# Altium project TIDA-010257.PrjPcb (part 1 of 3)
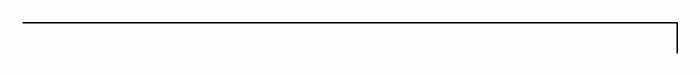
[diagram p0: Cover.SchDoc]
CopyrightYear: 2023; PCB_Layout: Hely Zhang; PCB_Rev: B; PRJ_Customer: Public Release; PRJ_Engineer: Hely Zhang; PRJ_Number: TIDA-010257; PRJ_Title: 10kW Vienna PFC; SCH_Rev: B; TechSupport: http://www.ti.com/support; TID: TIDA-010257
11 sheets, 481 parts. Net scope: hierarchical (ports join the sheet entries above them; power ports are global).
Board file: TIDA-010257.PcbDoc
Sheets:
  Cover.SchDoc
  Main.SchDoc
    PowerStage = PowerStage.SchDoc
    GateDrivers = GateDrivers.SchDoc
    IsolatedPower = IsolatedPower.SchDoc
    Hardware = Hardware.SchDoc
    EMCInputFilter = EMCInputFilter.SchDoc
    InputVoltageSensing = InputVoltageSensing.SchDoc
    OutputVoltageSensing = OutputVoltageSensing.SchDoc
    Controller = Controller.SchDoc
    AuxPower = AuxPower.SchDoc

## Sheet Cover.SchDoc: Cover
size 431 x 279 mm; Date: Not shown in title block; ApprovedBy: Not shown in title block; CheckedBy: Not shown in title block; Author: Not shown in title block; CompanyName: Not shown in title block; DrawnBy: Hely Zhang; Engineer: Not shown in title block; Organization: Not shown in title block; Address1: Not shown in title block; Address2: Not shown in title block; Address3: Not shown in title block; Address4: Not shown in title block; DocumentNumber: 1; Revision: Use project parameter SCH_Rev; SheetNumber: 1; SheetTotal: 11; PageSetup: Record=PageOptions¦CenterHorizontal=True¦CenterVertical=True¦PrintScale=1.00¦XCorrection=1.00¦YCorrection=1.00¦PrintKind=0¦BorderSize=5000000¦LeftOffset=0¦BottomOffset=0¦Orientation=2¦PaperLength=1000¦PaperWidth=1000¦Scale=100¦PaperSource=15¦PrintQuality=600¦MediaType=1¦DitherType=10¦PaperKind=Letter¦PrintScaleMode=1

## Sheet Main.SchDoc: Cover Page
size A4; Date: Not shown in title block; ApprovedBy: Not shown in title block; CheckedBy: Not shown in title block; Author: Not shown in title block; CompanyName: Not shown in title block; DrawnBy: Manish Bhardwaj; Engineer: Not shown in title block; Organization: Not shown in title block; Address1: Not shown in title block; Address2: Not shown in title block; Address3: Not shown in title block; Address4: Not shown in title block; DocumentNumber: 1; Revision: Use project parameter SCH_Rev; SheetNumber: 2; SheetTotal: 11; PageSetup: Record=PageOptions¦CenterHorizontal=True¦CenterVertical=True¦PrintScale=1.00¦XCorrection=1.00¦YCorrection=1.00¦PrintKind=0¦BorderSize=5000000¦LeftOffset=0¦BottomOffset=0¦Orientation=2¦PaperLength=1000¦PaperWidth=1000¦Scale=100¦PaperSource=15¦PrintQuality=-3¦MediaType=1¦DitherType=10¦PrintScaleMode=1¦PaperKind=Letter (8.5 x 11")¦PaperIndex=1
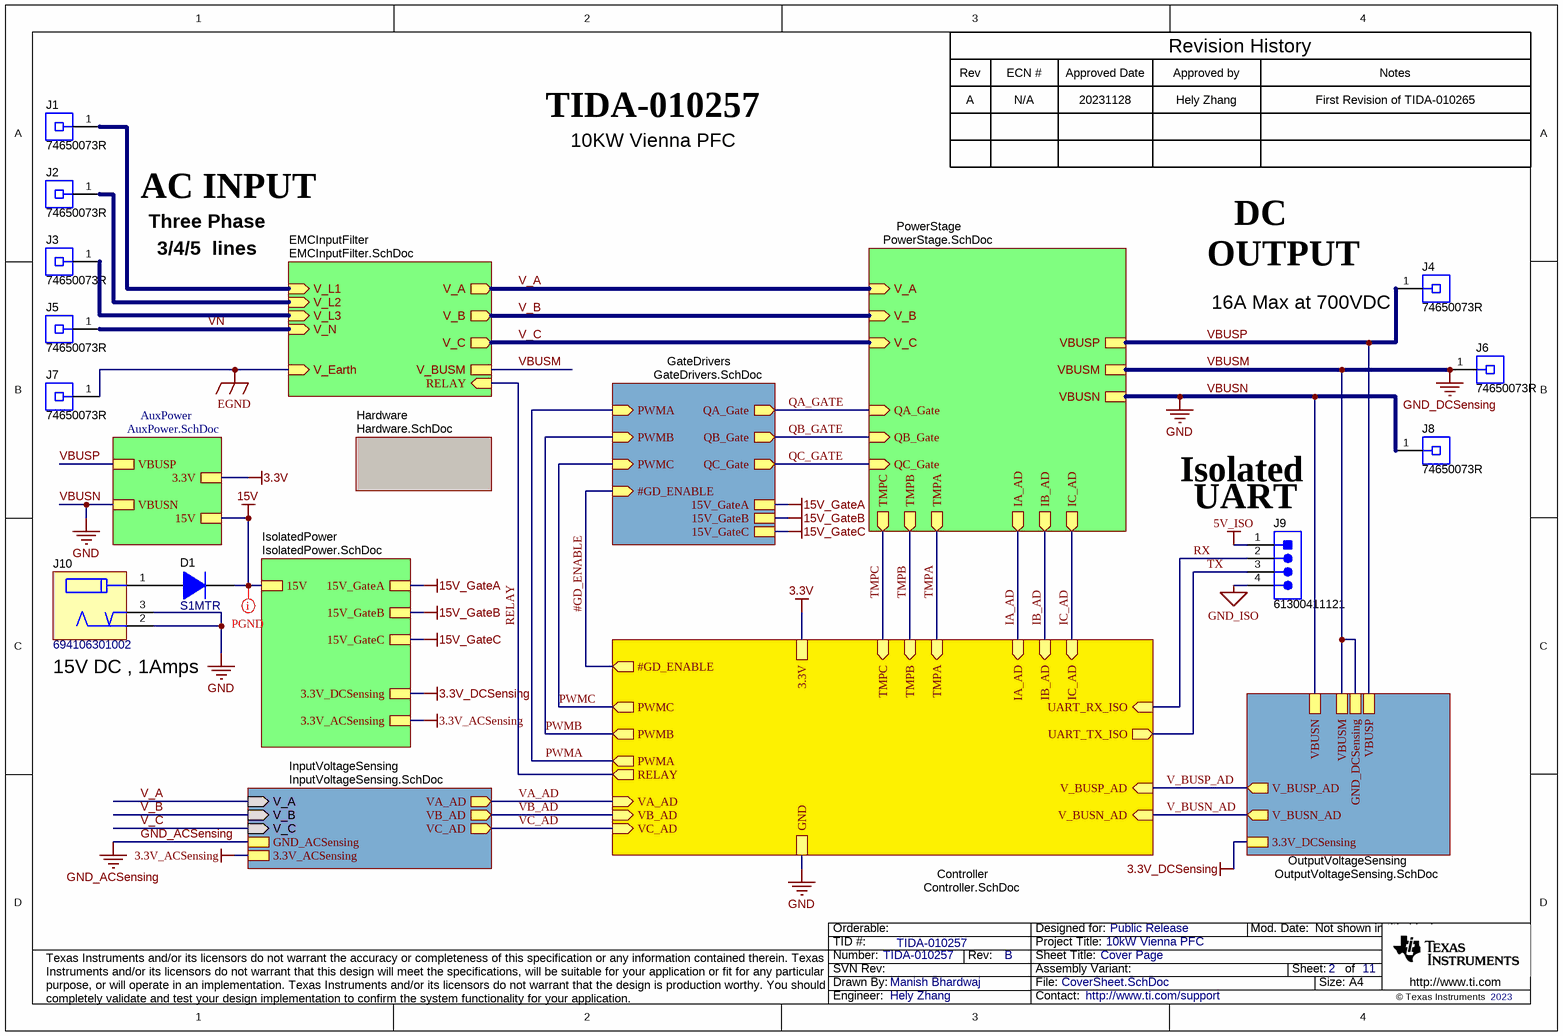
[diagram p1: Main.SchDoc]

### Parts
D1  S1MTR  [SMA]
J1  74650073R  [Wurth_WP-THRBU]
J2  74650073R  [Wurth_WP-THRBU]
J3  74650073R  [Wurth_WP-THRBU]
J4  74650073R  [Wurth_WP-THRBU]
J5  74650073R  [Wurth_WP-THRBU]
J6  74650073R  [Wurth_WP-THRBU]
J7  74650073R  [Wurth_WP-THRBU]
J8  74650073R  [Wurth_WP-THRBU]
J9  61300411121  [WURTH_61300411121]
J10  694106301002  [Wurth_694106301002]

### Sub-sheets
AuxPower = AuxPower.SchDoc: VBUSP, VBUSN, 15V, 3.3V
Controller = Controller.SchDoc: UART_RX_ISO (in), UART_TX_ISO (out), VA_AD (in), VB_AD (in), VC_AD (in), IC_AD (in), IB_AD (in), IA_AD (in), #GD_ENABLE (out), V_BUSN_AD (in), 3.3V, GND, TMPA (in), TMPB (in), TMPC (in), RELAY (out), V_BUSP_AD (in), PWMC (out), PWMB (out), PWMA (out)
EMCInputFilter = EMCInputFilter.SchDoc: V_N (in), V_L2 (in), V_L3 (in), V_L1 (in), V_Earth (in), V_C (out), V_B (out), V_A (out), V_BUSM, RELAY (in)
GateDrivers = GateDrivers.SchDoc: QA_Gate (out), #GD_ENABLE (in), QB_Gate (out), QC_Gate (out), 15V_GateA, 15V_GateB, 15V_GateC, PWMA (in), PWMB (in), PWMC (in)
Hardware = Hardware.SchDoc: no entries
InputVoltageSensing = InputVoltageSensing.SchDoc: V_A (in), V_B (in), V_C (in), VA_AD (out), VB_AD (out), VC_AD (out), GND_ACSensing, 3.3V_ACSensing
IsolatedPower = IsolatedPower.SchDoc: 15V, 15V_GateA, 15V_GateB, 15V_GateC, 3.3V_ACSensing, 3.3V_DCSensing
OutputVoltageSensing = OutputVoltageSensing.SchDoc: VBUSN, VBUSP, VBUSM, V_BUSP_AD (out), V_BUSN_AD (out), 3.3V_DCSensing, GND_DCSensing
PowerStage = PowerStage.SchDoc: V_A (in), V_B (in), V_C (in), VBUSP, VBUSM, VBUSN, QB_Gate (in), QC_Gate (in), IA_AD (out), IB_AD (out), IC_AD (out), QA_Gate (in), TMPA (out), TMPB (out), TMPC (out)

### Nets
3.3V: sheet Controller/3.3V, sheet AuxPower/3.3V
3.3V_ACSensing: sheet IsolatedPower/3.3V_ACSensing, sheet InputVoltageSensing/3.3V_ACSensing
3.3V_DCSensing: sheet IsolatedPower/3.3V_DCSensing, sheet OutputVoltageSensing/3.3V_DCSensing
5V_ISO: J9.1
15V: D1.1(K) ; sheet IsolatedPower/15V, sheet AuxPower/15V
15V_GateA: sheet GateDrivers/15V_GateA, sheet IsolatedPower/15V_GateA
15V_GateB: sheet GateDrivers/15V_GateB, sheet IsolatedPower/15V_GateB
15V_GateC: sheet GateDrivers/15V_GateC, sheet IsolatedPower/15V_GateC
EGND: J7.1 ; sheet EMCInputFilter/V_Earth
GND_ISO: J9.4
VBUSM: J6.1 ; sheet PowerStage/VBUSM, sheet EMCInputFilter/V_BUSM, sheet OutputVoltageSensing/VBUSM, sheet OutputVoltageSensing/GND_DCSensing  [also labelled GND_DCSensing]
VBUSN: J8.1 J10.2 J10.3 ; sheet PowerStage/VBUSN, sheet OutputVoltageSensing/VBUSN, sheet Controller/GND, sheet AuxPower/VBUSN  [also labelled GND]
#GD_ENABLE: sheet GateDrivers/#GD_ENABLE, sheet Controller/#GD_ENABLE
IA_AD: sheet PowerStage/IA_AD, sheet Controller/IA_AD
IB_AD: sheet PowerStage/IB_AD, sheet Controller/IB_AD
IC_AD: sheet PowerStage/IC_AD, sheet Controller/IC_AD
PWMA: sheet GateDrivers/PWMA, sheet Controller/PWMA
PWMB: sheet GateDrivers/PWMB, sheet Controller/PWMB
PWMC: sheet GateDrivers/PWMC, sheet Controller/PWMC
QA_GATE: sheet PowerStage/QA_Gate, sheet GateDrivers/QA_Gate
QB_GATE: sheet PowerStage/QB_Gate, sheet GateDrivers/QB_Gate
QC_GATE: sheet PowerStage/QC_Gate, sheet GateDrivers/QC_Gate
RELAY: sheet EMCInputFilter/RELAY, sheet Controller/RELAY
RX: J9.2 ; sheet Controller/UART_RX_ISO
TMPA: sheet PowerStage/TMPA, sheet Controller/TMPA
TMPB: sheet PowerStage/TMPB, sheet Controller/TMPB
TMPC: sheet PowerStage/TMPC, sheet Controller/TMPC
TX: J9.3 ; sheet Controller/UART_TX_ISO
V_A: sheet PowerStage/V_A, sheet EMCInputFilter/V_A, sheet InputVoltageSensing/V_A
V_B: sheet PowerStage/V_B, sheet EMCInputFilter/V_B, sheet InputVoltageSensing/V_B
V_BUSN_AD: sheet OutputVoltageSensing/V_BUSN_AD, sheet Controller/V_BUSN_AD
V_BUSP_AD: sheet OutputVoltageSensing/V_BUSP_AD, sheet Controller/V_BUSP_AD
V_C: sheet PowerStage/V_C, sheet EMCInputFilter/V_C, sheet InputVoltageSensing/V_C
V_L1: J1.1 ; sheet EMCInputFilter/V_L1
V_L2: J2.1 ; sheet EMCInputFilter/V_L2
V_L3: J3.1 ; sheet EMCInputFilter/V_L3
VA_AD: sheet InputVoltageSensing/VA_AD, sheet Controller/VA_AD
VB_AD: sheet InputVoltageSensing/VB_AD, sheet Controller/VB_AD
VBUSP: J4.1 ; sheet PowerStage/VBUSP, sheet OutputVoltageSensing/VBUSP, sheet AuxPower/VBUSP
VC_AD: sheet InputVoltageSensing/VC_AD, sheet Controller/VC_AD
VN: J5.1 ; sheet EMCInputFilter/V_N
NetD1_2: D1.2(A) J10.1

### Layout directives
net class PGND: 15V

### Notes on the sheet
- Revision History
- Rev
- A
- ECN #
- N/A
- Approved Date
- 20231128
- Approved by
- Hely Zhang
- Notes
- First Revision of TIDA-010265
- TIDA-010257
- 10KW Vienna PFC
- AC INPUT
- Three Phase
- 3/4/5  lines
- DC
- OUTPUT
- (near J4) 16A Max at 700VDC
- Isolated
- (near J9) UART
- (near J10) 15V DC , 1Amps

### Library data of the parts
D1 = CMP-0078438-1: Diode, Standard Recovery Rectifier, 1000 V, 1 A, SMA; Manufacturer: SMC Diode Solutions; SizeAreaWB_mm2: 37.3428; Vr_V: 1kV; SizeArea_mm2: 16.3228; AEC Qualified: N; TJmax_C: 175°C; AEC Category: Q101; Value: 1000V; SizeZ_mm: 2.87; Io_A: 1A; Vf_V: 1.1V; SizeY_mm: 2.92; SizeX_mm: 5.59
J1-J8 = CMP-0078526-1: Power Element Bush, M3, TH; Manufacturer: Wurth Elektronik; Gender: Female; Current_A: 50A; ContactFinish: Tin; CompType: Screw Terminal
J9 = CMP-0054798-2: Header, 2.54 mm, 4x1, Gold, TH; Manufacturer: Wurth Elektronik; Pitch_mm: 2.54; Gender: Male; Row_Count: 1; Cert_UL: Y; Shrouded: N
J10 = CMP-0054778-3: WR-DC DC Power Jack, R/A, TH; Manufacturer: Wurth Elektronik; Gender: Male

## Sheet PowerStage.SchDoc: Power Stage
size A3; Date: Not shown in title block; ApprovedBy: Not shown in title block; CheckedBy: Not shown in title block; Author: Not shown in title block; CompanyName: Not shown in title block; DrawnBy: Hely Zhang; Engineer: Not shown in title block; Organization: Not shown in title block; Address1: Not shown in title block; Address2: Not shown in title block; Address3: Not shown in title block; Address4: Not shown in title block; DocumentNumber: 1; Revision: Use project parameter SCH_Rev; SheetNumber: 4; SheetTotal: 11; PageSetup: Record=PageOptions¦CenterHorizontal=True¦CenterVertical=True¦PrintScale=1.00¦XCorrection=1.00¦YCorrection=1.00¦PrintKind=0¦BorderSize=5000000¦LeftOffset=0¦BottomOffset=0¦Orientation=2¦PaperLength=1000¦PaperWidth=1000¦Scale=100¦PaperSource=15¦PrintQuality=600¦MediaType=1¦DitherType=10¦PaperKind=Letter¦PrintScaleMode=1
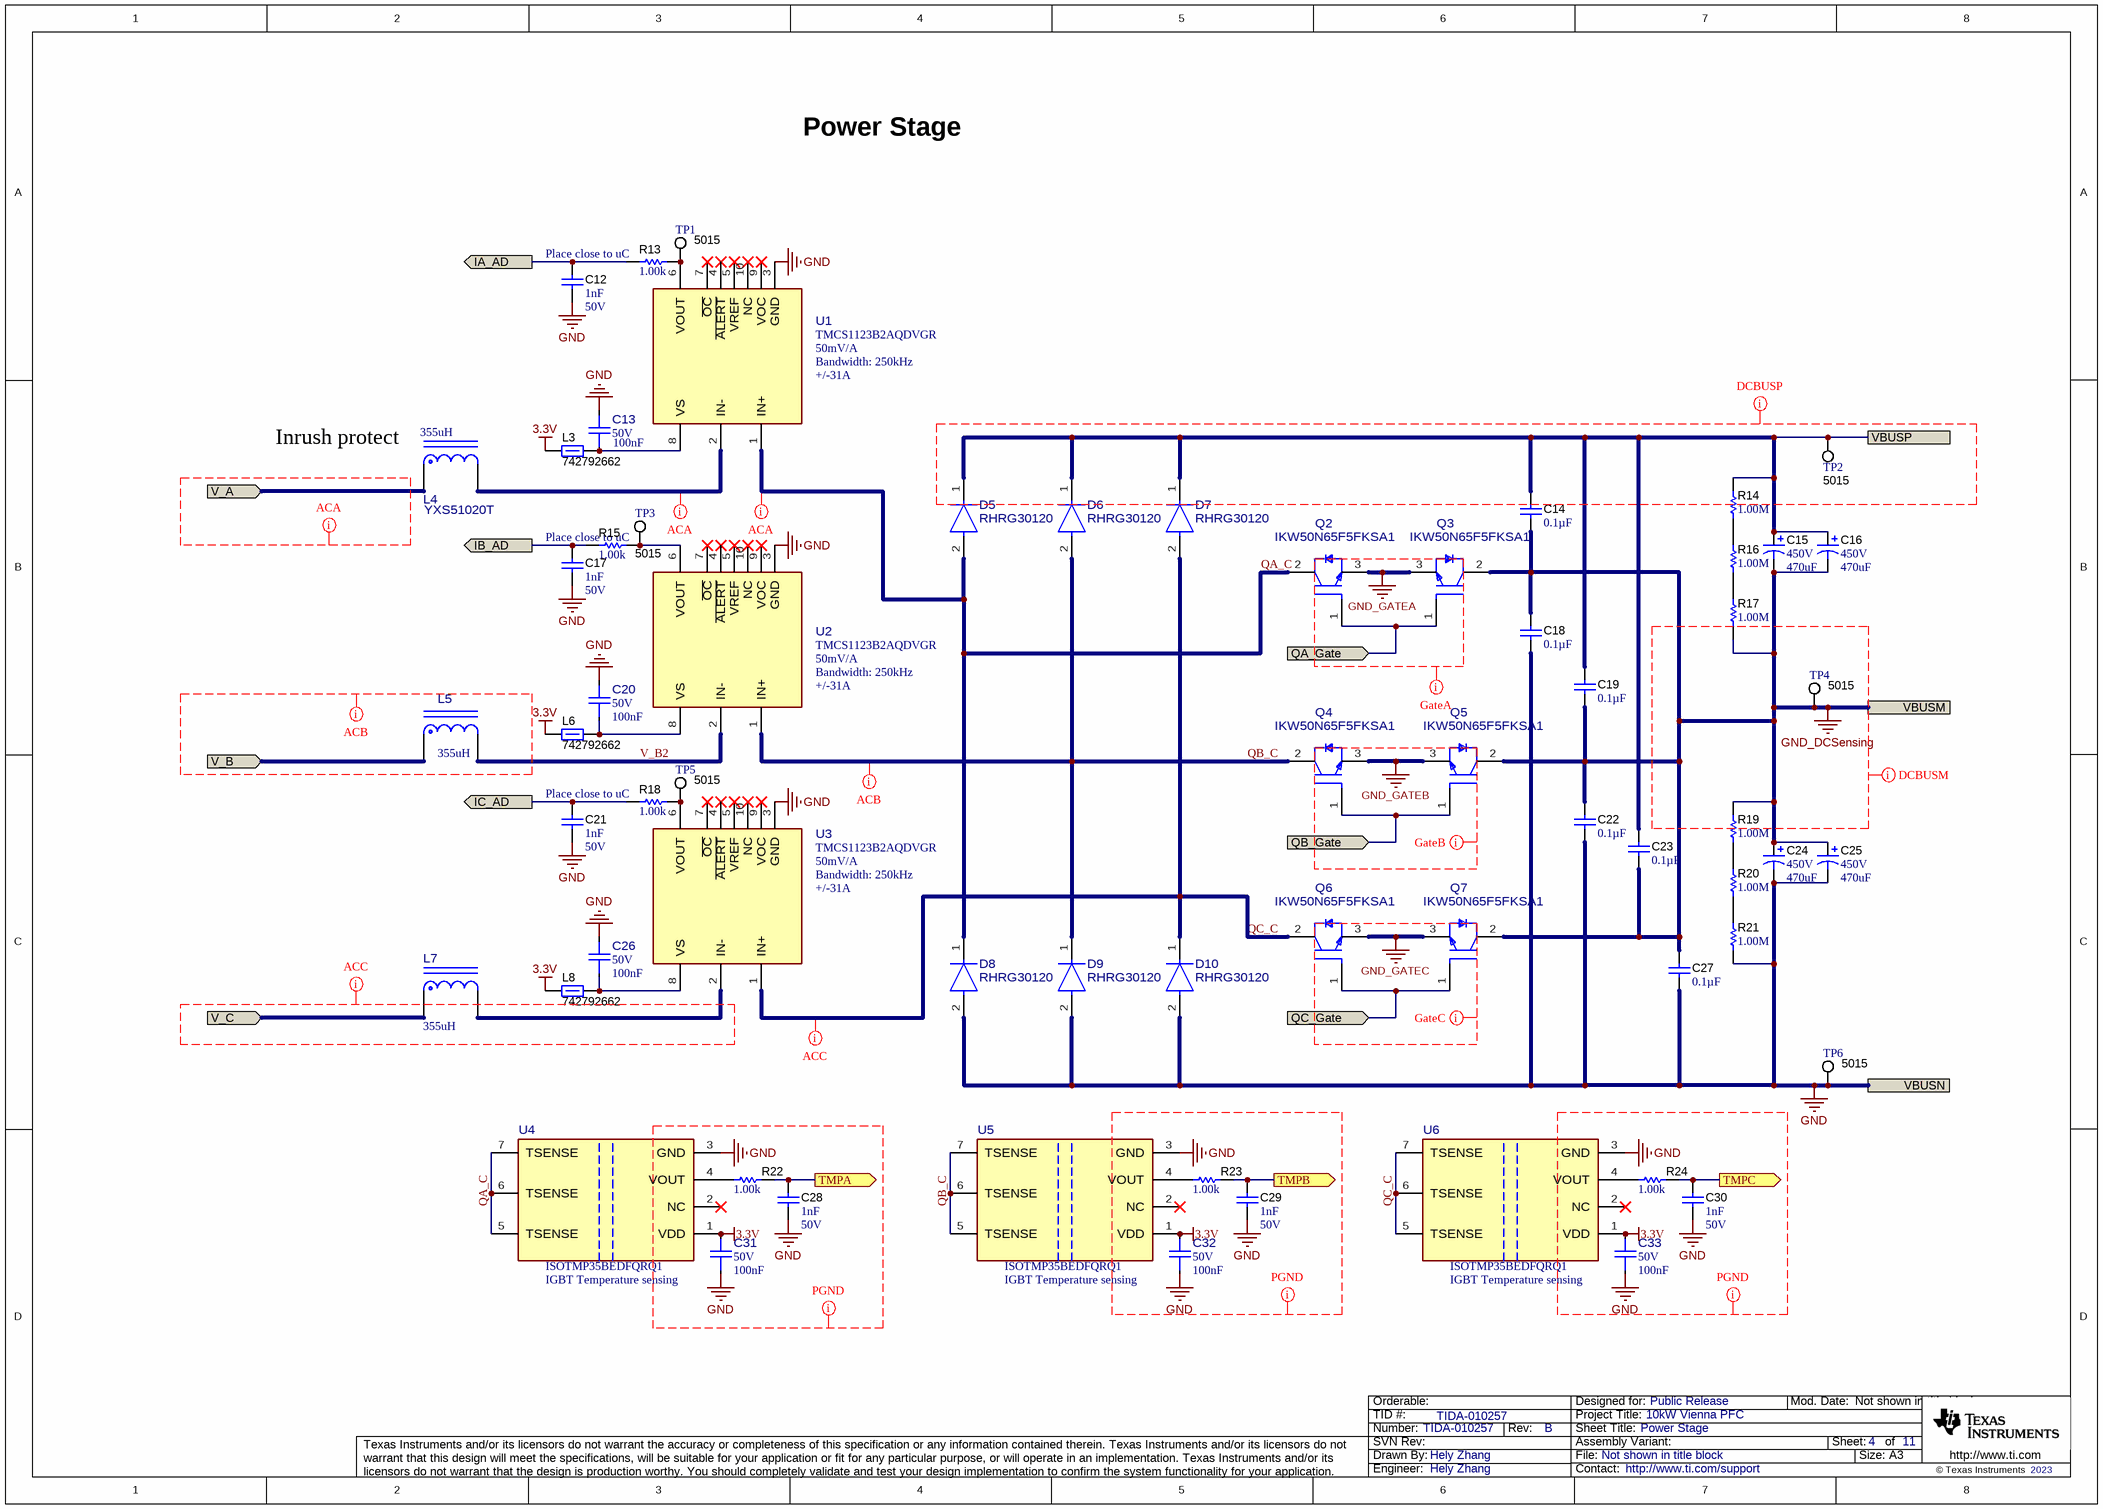
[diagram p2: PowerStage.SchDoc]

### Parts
C12  Cap_F: 1nF  VDC_V: 50V  [0603]  (hidden comment: GRM188R71H102KA01D)
C13  VDC_V: 50V  Cap_F: 100nF  [FP-GCM188R71H104KA57J_0603-MFG]  (hidden comment: GCM188R71H104KA57J)
C14  ValueDisplayed: 0.1µF  [WCAP-FTXX_P15PL20_1800x600]  (hidden comment: 890334025017)
C15  VDC_V: 450V  ValueDisplayed: 470uF  [157PUM-SI_3500x5000]  (hidden comment: MAL215757471E3)
C16  VDC_V: 450V  ValueDisplayed: 470uF  [157PUM-SI_3500x5000]  (hidden comment: MAL215757471E3)
C17  Cap_F: 1nF  VDC_V: 50V  [0603]  (hidden comment: GRM188R71H102KA01D)
C18  ValueDisplayed: 0.1µF  [WCAP-FTXX_P15PL20_1800x600]  (hidden comment: 890334025017)
C19  ValueDisplayed: 0.1µF  [WCAP-FTXX_P15PL20_1800x600]  (hidden comment: 890334025017)
C20  VDC_V: 50V  Cap_F: 100nF  [FP-GCM188R71H104KA57J_0603-MFG]  (hidden comment: GCM188R71H104KA57J)
C21  Cap_F: 1nF  VDC_V: 50V  [0603]  (hidden comment: GRM188R71H102KA01D)
C22  ValueDisplayed: 0.1µF  [WCAP-FTXX_P15PL20_1800x600]  (hidden comment: 890334025017)
C23  ValueDisplayed: 0.1µF  [WCAP-FTXX_P15PL20_1800x600]  (hidden comment: 890334025017)
C24  VDC_V: 450V  ValueDisplayed: 470uF  [157PUM-SI_3500x5000]  (hidden comment: MAL215757471E3)
C25  VDC_V: 450V  ValueDisplayed: 470uF  [157PUM-SI_3500x5000]  (hidden comment: MAL215757471E3)
C26  VDC_V: 50V  Cap_F: 100nF  [FP-GCM188R71H104KA57J_0603-MFG]  (hidden comment: GCM188R71H104KA57J)
C27  ValueDisplayed: 0.1µF  [WCAP-FTXX_P15PL20_1800x600]  (hidden comment: 890334025017)
C28  Cap_F: 1nF  VDC_V: 50V  [0603]  (hidden comment: GRM188R71H102KA01D)
C29  Cap_F: 1nF  VDC_V: 50V  [0603]  (hidden comment: GRM188R71H102KA01D)
C30  Cap_F: 1nF  VDC_V: 50V  [0603]  (hidden comment: GRM188R71H102KA01D)
C31  VDC_V: 50V  Cap_F: 100nF  [FP-GCM188R71H104KA57J_0603-MFG]  (hidden comment: GCM188R71H104KA57J)
C32  VDC_V: 50V  Cap_F: 100nF  [FP-GCM188R71H104KA57J_0603-MFG]  (hidden comment: GCM188R71H104KA57J)
C33  VDC_V: 50V  Cap_F: 100nF  [FP-GCM188R71H104KA57J_0603-MFG]  (hidden comment: GCM188R71H104KA57J)
D5  RHRG30120  [FP-RHRG30120-MFG_HOR]
D6  RHRG30120  [FP-RHRG30120-MFG_HOR]
D7  RHRG30120  [FP-RHRG30120-MFG_HOR]
D8  RHRG30120  [FP-RHRG30120-MFG_HOR]
D9  RHRG30120  [FP-RHRG30120-MFG_HOR]
D10  RHRG30120  [FP-RHRG30120-MFG_HOR]
L3  742792662  [0603]
L4  YXS51020T  value 355uH  [FP-YXS51020T_PTH_IND_58MM0_70MM0-MFG]
L5  value 355uH  [FP-YXS51020T_PTH_IND_58MM0_70MM0-MFG]  (hidden comment: YXS51020T)
L6  742792662  [0603]
L7  value 355uH  [FP-YXS51020T_PTH_IND_58MM0_70MM0-MFG]  (hidden comment: YXS51020T)
L8  742792662  [0603]
Q2  IKW50N65F5FKSA1  [FP-IKW50N65F5FKSA1_HOR_V1]
Q3  IKW50N65F5FKSA1  [FP-IKW50N65F5FKSA1_HOR_V2]
Q4  IKW50N65F5FKSA1  [FP-IKW50N65F5FKSA1_HOR_V1]
Q5  IKW50N65F5FKSA1  [FP-IKW50N65F5FKSA1_HOR_V2]
Q6  IKW50N65F5FKSA1  [FP-IKW50N65F5FKSA1_HOR_V1]
Q7  IKW50N65F5FKSA1  [FP-IKW50N65F5FKSA1_HOR_V2]
R13  ValueDisplayed: 1.00k  [0603]  (hidden comment: RC0603FR-071KL)
R14  ValueDisplayed: 1.00M  [0805_HV]  (hidden comment: ERJ-6ENF1004V)
R15  ValueDisplayed: 1.00k  [0603]  (hidden comment: RC0603FR-071KL)
R16  ValueDisplayed: 1.00M  [0805_HV]  (hidden comment: ERJ-6ENF1004V)
R17  ValueDisplayed: 1.00M  [0805_HV]  (hidden comment: ERJ-6ENF1004V)
R18  ValueDisplayed: 1.00k  [0603]  (hidden comment: RC0603FR-071KL)
R19  ValueDisplayed: 1.00M  [0805_HV]  (hidden comment: ERJ-6ENF1004V)
R20  ValueDisplayed: 1.00M  [0805_HV]  (hidden comment: ERJ-6ENF1004V)
R21  ValueDisplayed: 1.00M  [0805_HV]  (hidden comment: ERJ-6ENF1004V)
R22  ValueDisplayed: 1.00k  [0603]  (hidden comment: RC0603FR-071KL)
R23  ValueDisplayed: 1.00k  [0603]  (hidden comment: RC0603FR-071KL)
R24  ValueDisplayed: 1.00k  [0603]  (hidden comment: RC0603FR-071KL)
TP1  5015  [Testpoint_Keystone_Miniature]
TP2  5015  [Testpoint_Keystone_Miniature]
TP3  5015  [Testpoint_Keystone_Miniature]
TP4  5015  [Testpoint_Keystone_Miniature]
TP5  5015  [Testpoint_Keystone_Miniature]
TP6  5015  [Testpoint_Keystone_Miniature]
U1  TMCS1123B2AQDVGR  [DVG0010A-MFG]
U2  TMCS1123B2AQDVGR  [DVG0010A-MFG]
U3  TMCS1123B2AQDVGR  [DVG0010A-MFG]
U4  ISOTMP35BEDFQRQ1  [DFQ0007A-MFG]
U5  ISOTMP35BEDFQRQ1  [DFQ0007A-MFG]
U6  ISOTMP35BEDFQRQ1  [DFQ0007A-MFG]

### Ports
IA_AD (out), IB_AD (out), IC_AD (out), QA_Gate (in), QB_Gate (in), QC_Gate (in), TMPA (out), TMPB (out), TMPC (out), V_A (in), V_B (in), V_C (in), VBUSM, VBUSN, VBUSP

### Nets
3.3V: C31.2 C32.2 C33.2 L3.1 L6.1 L8.1 U4.1(VDD) U5.1(VDD) U6.1(VDD)
GND: C12.2 C13.2 C17.2 C18.2 C20.2 C21.2 C22.2 C24.2(-) C25.2(-) C26.2 C27.2 C28.2 C29.2 C30.2 C31.1 C32.1 C33.1 D8.2(ANODE) D9.2(ANODE) D10.2(ANODE) R21.1 TP6.1 U1.3(GND) U2.3(GND) U3.3(GND) U4.3(GND) U5.3(GND) U6.3(GND) ; port VBUSN  [project net VBUSN]
GND_DCSensing: C14.2 C15.2(-) C16.2(-) C18.1 C19.2 C22.1 C23.2 C24.1(+) C25.1(+) C27.1 Q3.2(C) Q5.2(C) Q7.2(C) R17.1 R19.2 TP4.1 ; port VBUSM  [project net VBUSM]
GND_GATEA: Q2.3(E) Q3.3(E)
GND_GATEB: Q4.3(E) Q5.3(E)
GND_GATEC: Q6.3(E) Q7.3(E)
IA_AD: C12.1 R13.1 ; port IA_AD
IB_AD: C17.1 R15.1 ; port IB_AD
IC_AD: C21.1 R18.1 ; port IC_AD
QA_C: D5.2(ANODE) D8.1(CATHODE) Q2.2(C) U1.1(IN+) U4.5(TSENSE) U4.6(TSENSE) U4.7(TSENSE)
QA_GATE: Q2.1(G) Q3.1(G) ; port QA_Gate
QB_C: D6.2(ANODE) D9.1(CATHODE) Q4.2(C) U2.1(IN+) U5.5(TSENSE) U5.6(TSENSE) U5.7(TSENSE)
QB_GATE: Q4.1(G) Q5.1(G) ; port QB_Gate
QC_C: D7.2(ANODE) D10.1(CATHODE) Q6.2(C) U3.1(IN+) U6.5(TSENSE) U6.6(TSENSE) U6.7(TSENSE)
QC_GATE: Q6.1(G) Q7.1(G) ; port QC_Gate
TMPA: C28.1 R22.1 ; port TMPA
TMPB: C29.1 R23.1 ; port TMPB
TMPC: C30.1 R24.1 ; port TMPC
V_A: L4.1 ; port V_A
V_B: L5.1 ; port V_B
V_B2: L5.2 U2.2(IN-)
V_C: L7.1 ; port V_C
VBUSP: C14.1 C15.1(+) C16.1(+) C19.1 C23.1 D5.1(CATHODE) D6.1(CATHODE) D7.1(CATHODE) R14.2 TP2.1 ; port VBUSP
NetC13_1: C13.1 L3.2 U1.8(VS)
NetC20_1: C20.1 L6.2 U2.8(VS)
NetC26_1: C26.1 L8.2 U3.8(VS)
NetL4_2: L4.2 U1.2(IN-)
NetL7_2: L7.2 U3.2(IN-)
NetR13_2: R13.2 TP1.1 U1.6(VOUT)
NetR14_1: R14.1 R16.2
NetR15_2: R15.2 TP3.1 U2.6(VOUT)
NetR16_1: R16.1 R17.2
NetR18_2: R18.2 TP5.1 U3.6(VOUT)
NetR19_1: R19.1 R20.2
NetR20_1: R20.1 R21.2
NetR22_2: R22.2 U4.4(VOUT)
NetR23_2: R23.2 U5.4(VOUT)
NetR24_2: R24.2 U6.4(VOUT)

Not connected (* = marked no-connect by the designer): U1 4(~{ALERT})* 5(VREF)* 7(~{OC})* 9(VOC)* 10(NC)*; U2 4(~{ALERT})* 5(VREF)* 7(~{OC})* 9(VOC)* 10(NC)*; U3 4(~{ALERT})* 5(VREF)* 7(~{OC})* 9(VOC)* 10(NC)*; U4 2(NC)*; U5 2(NC)*; U6 2(NC)*

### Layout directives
net class DCBUSP: (no net found under the mark)
net class GateA: GND_GATEA
net class GateB: GND_GATEB
net class GateC: GND_GATEC
net class DCBUSM: GND_DCSensing
net class PGND: 3.3V, GND
net class ACC: (no net found under the mark), QC_C
net class ACA: (no net found under the mark), NetL4_2, QA_C
net class ACB: (no net found under the mark), QB_C

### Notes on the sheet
- Power Stage
- (near R13) Place close to uC
- (near U1) 50mV/A
- (near U1) Bandwidth: 250kHz
- (near U1) +/-31A
- Inrush protect
- Place close to uC
- (near U2) 50mV/A
- (near U2) Bandwidth: 250kHz
- (near U2) +/-31A
- (near R18) Place close to uC
- (near U3) 50mV/A
- (near U3) Bandwidth: 250kHz
- (near U3) +/-31A
- IGBT Temperature sensing

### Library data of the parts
C12 C17 C21 C28-C30 = CMP-0007432-5: CAP, CERM, 1000 pF, 50 V, +/- 10%, X7R, 0603; Manufacturer: MuRata; TaMin_C: -55°C; Polarized: N; SizeAreaWB_mm2: 4.68; Value1: Unknown; U/M: EA; Value: 1000pF; TaMax_C: 125°C; SizeZ_mm: 1; SizeX_mm: 1.6; SizeY_mm: 0.8; SizeArea_mm2: 1.28; AEC Category: Q200
C13 C20 C26 C31-C33 = CMP-0095617-1: 0603 50 V 0.1 uF X7R ±10% Tolerance SMT Multilayer Ceramic Capacitor; Manufacturer: Murata; TempCo: 15%; SizeZ_mm: 0.9mm; AEC Qualified: No; ValueDisplayed: 0.1uF; Value: 100nF
C14 C18 C19 C22 C23 C27 = CMP-0860742-1: CAP, Film, 0.1 µF, 310 VAC/ VDC,+/- 10%, TH; Manufacturer: Wurth Elektronik; VAC: 310; SizeZ_mm: 12.5; Cap_F: 100nF; Polarized: N; SizeArea_mm2: 108; SizeX_mm: 18; TaMax_C: 105°C; SizeAreaWB_mm2: 160; Value: 0.1uF; Cap_Case: 18x6x12mm; TaMin_C: -40°C; AEC Category: Q200; SizeY_mm: 6
C15 C16 C24 C25 = CMP-0010144-2: CAP, AL, 470 uF, 450 V, +/- 20%, 0.42 ohm, TH; Manufacturer: Vishay-Bccomponents; TaMin_C: -25°C; ESR_ohm: 0.42; Polarized: Y; SizeAreaWB_mm2: 1369; U/M: EA; Value: 470uF; TaMax_C: 85°C; SizeZ_mm: 52; SizeX_mm: 35; Cap_Case: 35x50mm; SizeArea_mm2: 1225; CompType: Capacitor; AEC Qualified: N; Cap_F: 470µF; IRMS_A: 2.6A; AEC Category: Q200
D5-D10 = CMP-0122869-4: Diode 1200 V 30A Through Hole TO-247-2; Manufacturer: onsemi; Obsolete Part: true; AEC Qualified: No; SizeZ_mm: 24.75mm; TJmax_C: 175°C; Vf_V: 1.2kV; Dc Blocking Voltage: 1200V; Max Surge Forward Current: 300A; Peak Reverse Current: 250uA; Standoff Height: 3.69mm; AEC Category: Q101
L3 L6 L8 = CMP-0003201-2: Ferrite Bead, 1000 ohm @ 100 MHz, 0.6 A, 0603; Manufacturer: Wurth Elektronik; Ztyp@1GHz_Ohm: 185.971; ZTyp@100MHz_Ohm: 1k; SizeAreaWB_mm2: 4.68; DCR_ohm: 0.3; Value1: 0.3 ohm; Imax_A: 600mA; SizeZ_mm: 1; SizeX_mm: 1.6; SizeY_mm: 0.8; Value2: 0.6A; SizeArea_mm2: 1.28
L4 L5 L7 = CMP-0122551-1: PFC INDUCTANCE 350uH 31A; Manufacturer: YAXIN ELECTRONICS; AEC Qualified: No; DCR_ohm: 25m; Ind_H: 355µH; SizeZ_mm: 60mm; Test Frequency: 100kHz; Tolerance_%: 12%
Q2-Q7 = CMP-0122917-3: IGBT 650 V 80 A 305 W Through Hole PG-TO247-3; Manufacturer: Infineon; AEC Qualified: No; SizeZ_mm: 25.5mm; Value: 650V; Collector Current: 80A; Power_W: 305W; Rthja Max: 40K/W; Standoff Height: 4.1mm; TJmax_C: +175°C; Turn Off Delay Time: 175ns; Turn On Delay Time: 21ns; Vcesat1_V: 1.6V; ChMode: Enhancement
R13 R15 R18 R22-R24 = CMP-0022895-5: RES, 1.00 k, 1%, 0.1 W, 0603; Manufacturer: Yageo; Power_W: 100mW; TempCo: 100 ppm/C; Value_Code: 1k00; Value: 1.00k; EIA_Code: E96; Res_ohm: 1k; SizeX_mm: 1.6; SizeY_mm: 0.8; SizeZ_mm: 1; Value2: 0.1W; SizeArea_mm2: 1.28; AEC Qualified: N; VDC_V: 75V; AEC Category: Q200; SizeAreaWB_mm2: 4.68
R14 R16 R17 R19-R21 = CMP-0021522-3: RES, 1.00 M, 1%, 0.125 W, AEC-Q200 Grade 0, 0805; Manufacturer: Panasonic; Power_W: 125mW; TempCo: 100 ppm/C; Value_Code: 1M00; Value: 1.00Meg; EIA_Code: E96; Res_ohm: 1M; SizeX_mm: 2; SizeY_mm: 1.25; SizeZ_mm: 1.45; Value2: 0.125W; SizeArea_mm2: 2.5; AEC Qualified: Y; AEC Category: Q200; AEC Grade: 0; SizeAreaWB_mm2: 6.75
TP1-TP6 = CMP-0055152-2: Test Point, Miniature, SMT; Manufacturer: Keystone Electronics; CT: TRUE; Green_Lifecycle: Active; Green_REACh: Passed; CNHeader: FALSE
U1-U3 = CMP-0121162-1: Precision 250kHz Hall-Effect Current Sensor With ±1.3kV Reinforced Isolation Working Voltage, Overcurrent Detection and Ambient Field Rejection; Manufacturer: Texas Instruments; SizeZ_mm: 2.65mm; AEC Qualified: No; Accuracy: 0.1%; Coil Resistance: 0.7mΩ; Current Sensitivity: 50mV/A; Max Sensing Current: 65A; Max Supply Voltage: 5.5V; Min Supply Voltage: 3V; Operating Supply Current: 11mA; Sensing Method: Hall Effect; Sensor Output: Analog Voltage; Standoff Height: 0.1mm; TaMax_C: +125°C; TaMin_C: -40°C; TJmax_C: +165°C
U4-U6 = CMP-0122473-1: Automotive ±1.5°C, 3-kVRMS Isolated Temperature Sensor With Analog Output With < 2 Seconds Response Time and 500VRMS Working Voltage; Manufacturer: Texas Instruments; SizeZ_mm: 1.75mm; AEC Qualified: Yes; AEC Grade: Grade 0; Max Supply Voltage: 5.5V; Min Supply Voltage: 2.3V; Operating Supply Current: 10uA; Sensor Output: Analog Voltage; Standoff Height: 0.11mm; TaMax_C: +150°C; TaMin_C: -40°C; TJmax_C: +155°C

## Sheet GateDrivers.SchDoc: Gate Drivers
size A4; Date: Not shown in title block; ApprovedBy: Not shown in title block; CheckedBy: Not shown in title block; Author: Not shown in title block; CompanyName: Not shown in title block; DrawnBy: Hely Zhang; Engineer: Not shown in title block; Organization: Not shown in title block; Address1: Not shown in title block; Address2: Not shown in title block; Address3: Not shown in title block; Address4: Not shown in title block; DocumentNumber: 1; Revision: Use project parameter SCH_Rev; SheetNumber: 10; SheetTotal: 11; PageSetup: Record=PageOptions¦CenterHorizontal=True¦CenterVertical=True¦PrintScale=1.00¦XCorrection=1.00¦YCorrection=1.00¦PrintKind=0¦BorderSize=5000000¦LeftOffset=0¦BottomOffset=0¦Orientation=2¦PaperLength=1000¦PaperWidth=1000¦Scale=100¦PaperSource=15¦PrintQuality=600¦MediaType=1¦DitherType=10¦PaperKind=Letter¦PrintScaleMode=1
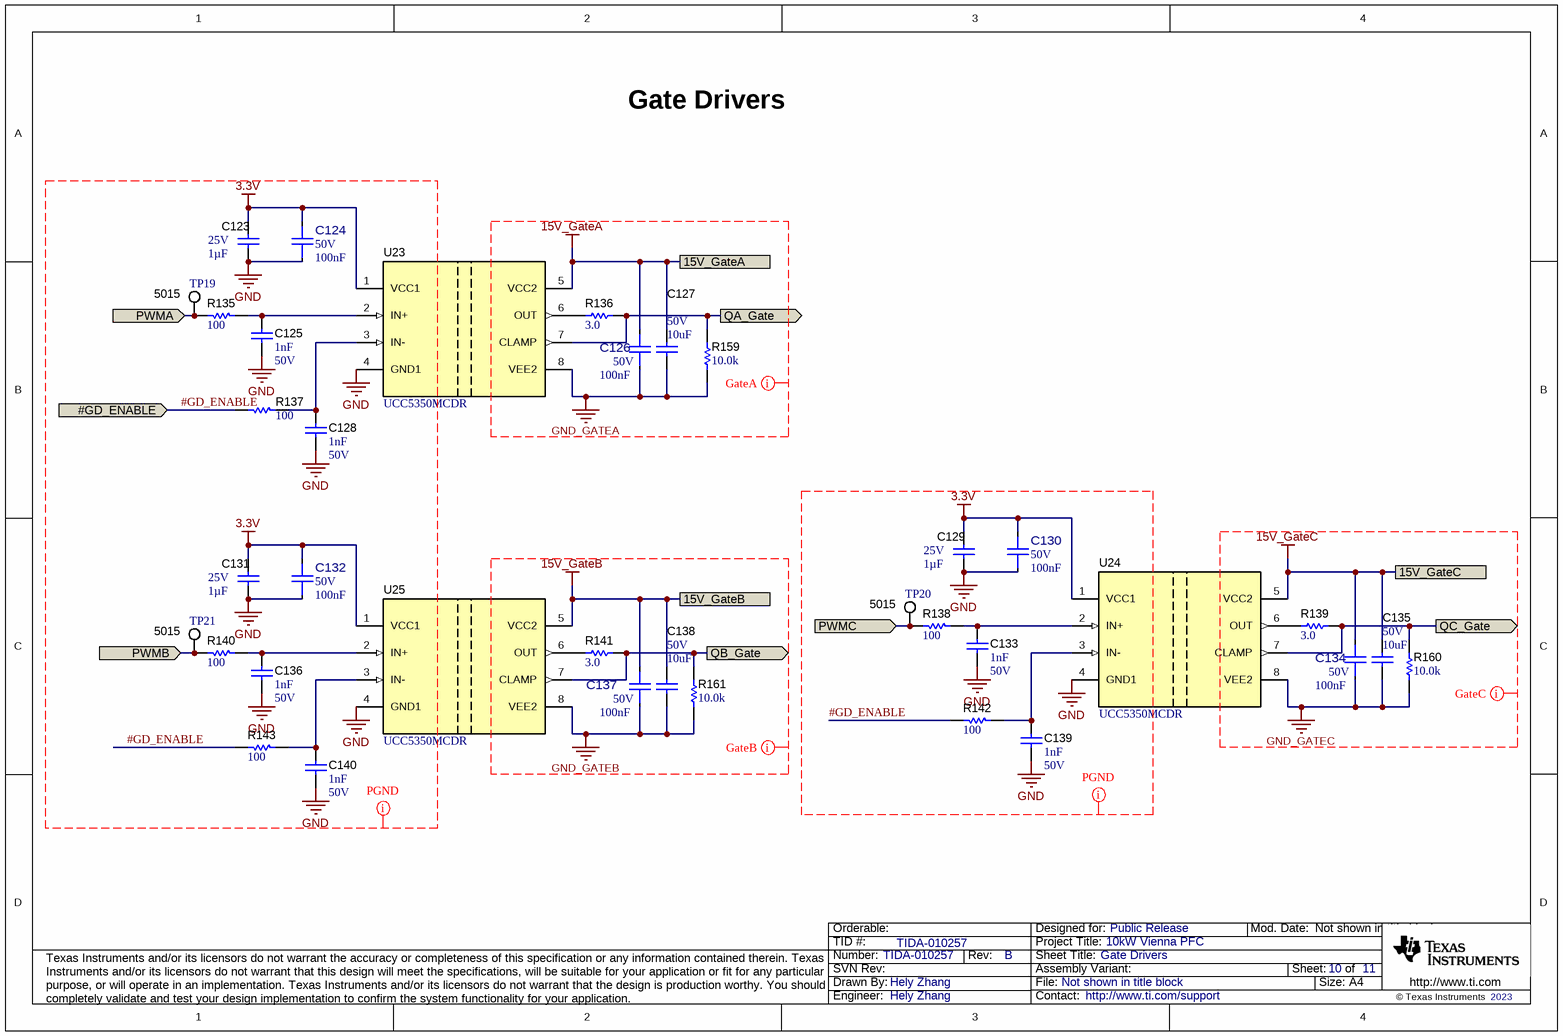
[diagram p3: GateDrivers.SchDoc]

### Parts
C123  VDC_V: 25V  Cap_F: 1µF  [0603]  (hidden comment: GRJ188R71E105KE11D)
C124  VDC_V: 50V  Cap_F: 100nF  [FP-GCM188R71H104KA57J_0603-MFG]  (hidden comment: GCM188R71H104KA57J)
C125  Cap_F: 1nF  VDC_V: 50V  [0603]  (hidden comment: GRM188R71H102KA01D)
C126  VDC_V: 50V  Cap_F: 100nF  [FP-GCM188R71H104KA57J_0603-MFG]  (hidden comment: GCM188R71H104KA57J)
C127  VDC_V: 50V  ValueDisplayed: 10uF  [1206_180]  (hidden comment: GRM31CR61H106KA12L)
C128  Cap_F: 1nF  VDC_V: 50V  [0603]  (hidden comment: GRM188R71H102KA01D)
C129  VDC_V: 25V  Cap_F: 1µF  [0603]  (hidden comment: GRJ188R71E105KE11D)
C130  VDC_V: 50V  Cap_F: 100nF  [FP-GCM188R71H104KA57J_0603-MFG]  (hidden comment: GCM188R71H104KA57J)
C131  VDC_V: 25V  Cap_F: 1µF  [0603]  (hidden comment: GRJ188R71E105KE11D)
C132  VDC_V: 50V  Cap_F: 100nF  [FP-GCM188R71H104KA57J_0603-MFG]  (hidden comment: GCM188R71H104KA57J)
C133  Cap_F: 1nF  VDC_V: 50V  [0603]  (hidden comment: GRM188R71H102KA01D)
C134  VDC_V: 50V  Cap_F: 100nF  [FP-GCM188R71H104KA57J_0603-MFG]  (hidden comment: GCM188R71H104KA57J)
C135  VDC_V: 50V  ValueDisplayed: 10uF  [1206_180]  (hidden comment: GRM31CR61H106KA12L)
C136  Cap_F: 1nF  VDC_V: 50V  [0603]  (hidden comment: GRM188R71H102KA01D)
C137  VDC_V: 50V  Cap_F: 100nF  [FP-GCM188R71H104KA57J_0603-MFG]  (hidden comment: GCM188R71H104KA57J)
C138  VDC_V: 50V  ValueDisplayed: 10uF  [1206_180]  (hidden comment: GRM31CR61H106KA12L)
C139  Cap_F: 1nF  VDC_V: 50V  [0603]  (hidden comment: GRM188R71H102KA01D)
C140  Cap_F: 1nF  VDC_V: 50V  [0603]  (hidden comment: GRM188R71H102KA01D)
R135  ValueDisplayed: 100  [0603]  (hidden comment: RC0603FR-07100RL)
R136  ValueDisplayed: 3.0  [1206]  (hidden comment: CRCW12063R00JNEA)
R137  ValueDisplayed: 100  [0603]  (hidden comment: RC0603FR-07100RL)
R138  ValueDisplayed: 100  [0603]  (hidden comment: RC0603FR-07100RL)
R139  ValueDisplayed: 3.0  [1206]  (hidden comment: CRCW12063R00JNEA)
R140  ValueDisplayed: 100  [0603]  (hidden comment: RC0603FR-07100RL)
R141  ValueDisplayed: 3.0  [1206]  (hidden comment: CRCW12063R00JNEA)
R142  ValueDisplayed: 100  [0603]  (hidden comment: RC0603FR-07100RL)
R143  ValueDisplayed: 100  [0603]  (hidden comment: RC0603FR-07100RL)
R159  ValueDisplayed: 10.0k  [0603]  (hidden comment: RC0603FR-0710KL)
R160  ValueDisplayed: 10.0k  [0603]  (hidden comment: RC0603FR-0710KL)
R161  ValueDisplayed: 10.0k  [0603]  (hidden comment: RC0603FR-0710KL)
TP19  5015  [Testpoint_Keystone_Miniature]
TP20  5015  [Testpoint_Keystone_Miniature]
TP21  5015  [Testpoint_Keystone_Miniature]
U23  UCC5350MCDR  [D0008B_HV]
U24  UCC5350MCDR  [D0008B_HV]
U25  UCC5350MCDR  [D0008B_HV]

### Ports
15V_GateA, 15V_GateB, 15V_GateC, #GD_ENABLE (in), PWMA (in), PWMB (in), PWMC (in), QA_Gate (out), QB_Gate (out), QC_Gate (out)

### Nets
3.3V: C123.1 C124.2 C129.1 C130.2 C131.1 C132.2 U23.1(VCC1) U24.1(VCC1) U25.1(VCC1)
15V_GateA: C126.2 C127.1 U23.5(VCC2) ; port 15V_GateA
15V_GateB: C137.2 C138.1 U25.5(VCC2) ; port 15V_GateB
15V_GateC: C134.2 C135.1 U24.5(VCC2) ; port 15V_GateC
GND: C123.2 C124.1 C125.2 C128.2 C129.2 C130.1 C131.2 C132.1 C133.2 C136.2 C139.2 C140.2 U23.4(GND1) U24.4(GND1) U25.4(GND1)  [project net VBUSN]
GND_GATEA: C126.1 C127.2 R159.2 U23.8(VEE2)
GND_GATEB: C137.1 C138.2 R161.2 U25.8(VEE2)
GND_GATEC: C134.1 C135.2 R160.2 U24.8(VEE2)
#GD_ENABLE: R137.2 R142.2 R143.2 ; port #GD_ENABLE
PWMA: R135.2 TP19.1 ; port PWMA
PWMB: R140.2 TP21.1 ; port PWMB
PWMC: R138.2 TP20.1 ; port PWMC
QA_GATE: R136.2 R159.1 U23.7(CLAMP) ; port QA_Gate
QB_GATE: R141.2 R161.1 U25.7(CLAMP) ; port QB_Gate
QC_GATE: R139.2 R160.1 U24.7(CLAMP) ; port QC_Gate
NetC125_1: C125.1 R135.1 U23.2(IN+)
NetC128_1: C128.1 R137.1 U23.3(IN-)
NetC133_1: C133.1 R138.1 U24.2(IN+)
NetC136_1: C136.1 R140.1 U25.2(IN+)
NetC139_1: C139.1 R142.1 U24.3(IN-)
NetC140_1: C140.1 R143.1 U25.3(IN-)
NetR136_1: R136.1 U23.6(OUT)
NetR139_1: R139.1 U24.6(OUT)
NetR141_1: R141.1 U25.6(OUT)

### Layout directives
net class GateA: 15V_GateA, GND_GATEA
net class GateB: 15V_GateB, GND_GATEB
net class GateC: 15V_GateC, GND_GATEC
net class PGND: 3.3V, #GD_ENABLE, GND

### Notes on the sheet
- Gate Drivers

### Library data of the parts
C123 C129 C131 = CMP-0079720-2: CAP, CERM, 1 µF, 25 V,+/- 10%, X7R, 0603; Manufacturer: MuRata; AEC Category: Q200; TaMin_C: -55°C; AEC Qualified: N; SizeAreaWB_mm2: 4.68; SizeArea_mm2: 1.28; Value: 1uF; SizeZ_mm: 1; SizeX_mm: 1.6; U/M: EA; MFG_Status: TI_Obsolete; SizeY_mm: 0.8; TaMax_C: 125°C
C124 C126 C130 C132 C134 C137 = CMP-0095617-1: as C13 on sheet PowerStage
C125 C128 C133 C136 C139 C140 = CMP-0007432-5: as C12 on sheet PowerStage
C127 C135 C138 = CMP-0008954-2: CAP, CERM, 10 uF, 50 V, +/- 10%, X5R, 1206; Manufacturer: MuRata; TaMin_C: -55°C; Polarized: N; SizeAreaWB_mm2: 10.92; Value1: Unknown; U/M: EA; Value: 10uF; TaMax_C: 85°C; SizeZ_mm: 1.8; SizeX_mm: 3.2; SizeY_mm: 1.6; Cap_Case: 1206; SizeArea_mm2: 5.12; Cap_F: 10µF; AEC Category: Q200
R135 R137 R138 R140 R142 R143 = CMP-0022736-4: RES, 100, 1%, 0.1 W, 0603; Manufacturer: Yageo; Power_W: 100mW; TempCo: 100 ppm/C; Value_Code: 100R; Value: 100; EIA_Code: E96; SizeX_mm: 1.6; SizeY_mm: 0.8; SizeZ_mm: 1; Value2: 0.1W; SizeArea_mm2: 1.28; AEC Qualified: N; VDC_V: 75V; AEC Category: Q200; SizeAreaWB_mm2: 4.68
R136 R139 R141 = CMP-0018676-1: RES, 3.0, 5%, 0.25 W, 1206; Manufacturer: Vishay-Dale; Power_W: 250mW; TempCo: 200 ppm/C; Value_Code: 3R00; U/M: EA; Value: 3.0; EIA_Code: E24; Res_ohm: 3; SizeX_mm: 3.2; SizeY_mm: 1.6; SizeZ_mm: 1.35; Value2: 0.25W; SizeArea_mm2: 5.12; VDC_V: 200V; AEC Category: Q200
R159-R161 = CMP-0022746-5: RES, 10.0 k, 1%, 0.1 W, 0603; Manufacturer: Yageo; Power_W: 100mW; TempCo: 100 ppm/C; Value_Code: 10k0; Value: 10.0k; EIA_Code: E96; Res_ohm: 10k; SizeX_mm: 1.6; SizeY_mm: 0.8; SizeZ_mm: 1; Value2: 0.1W; SizeArea_mm2: 1.28; AEC Qualified: N; VDC_V: 75V; AEC Category: Q200; SizeAreaWB_mm2: 4.68
TP19-TP21 = CMP-0055152-2: as TP1 on sheet PowerStage
U23-U25 = CMP-0065064-4: 4.3-A, 3-kVRMS Isolated Single-Channel Gate Drivers, D0008B (SOIC-8); Manufacturer: Texas Instruments; SizeX_mm: 6.0; SizeY_mm: 4.9; CompType: IC; SizeZ_mm: 1.75; SizeArea_mm2: 29.4; SizeAreaWB_mm2: 55.2; U/M: EA

## Sheet IsolatedPower.SchDoc: Board Bias Power Supply
size A4; Date: Not shown in title block; ApprovedBy: Not shown in title block; CheckedBy: Not shown in title block; Author: Not shown in title block; CompanyName: Not shown in title block; DrawnBy: Manish Bhardwaj; Engineer: Not shown in title block; Organization: Not shown in title block; Address1: Not shown in title block; Address2: Not shown in title block; Address3: Not shown in title block; Address4: Not shown in title block; DocumentNumber: 1; Revision: Use project parameter SCH_Rev; SheetNumber: 6; SheetTotal: 11; PageSetup: Record=PageOptions¦CenterHorizontal=True¦CenterVertical=True¦PrintScale=1.00¦XCorrection=1.00¦YCorrection=1.00¦PrintKind=0¦BorderSize=5000000¦LeftOffset=0¦BottomOffset=0¦Orientation=2¦PaperLength=1000¦PaperWidth=1000¦Scale=100¦PaperSource=15¦PrintQuality=600¦MediaType=1¦DitherType=10¦PaperKind=Letter¦PrintScaleMode=1
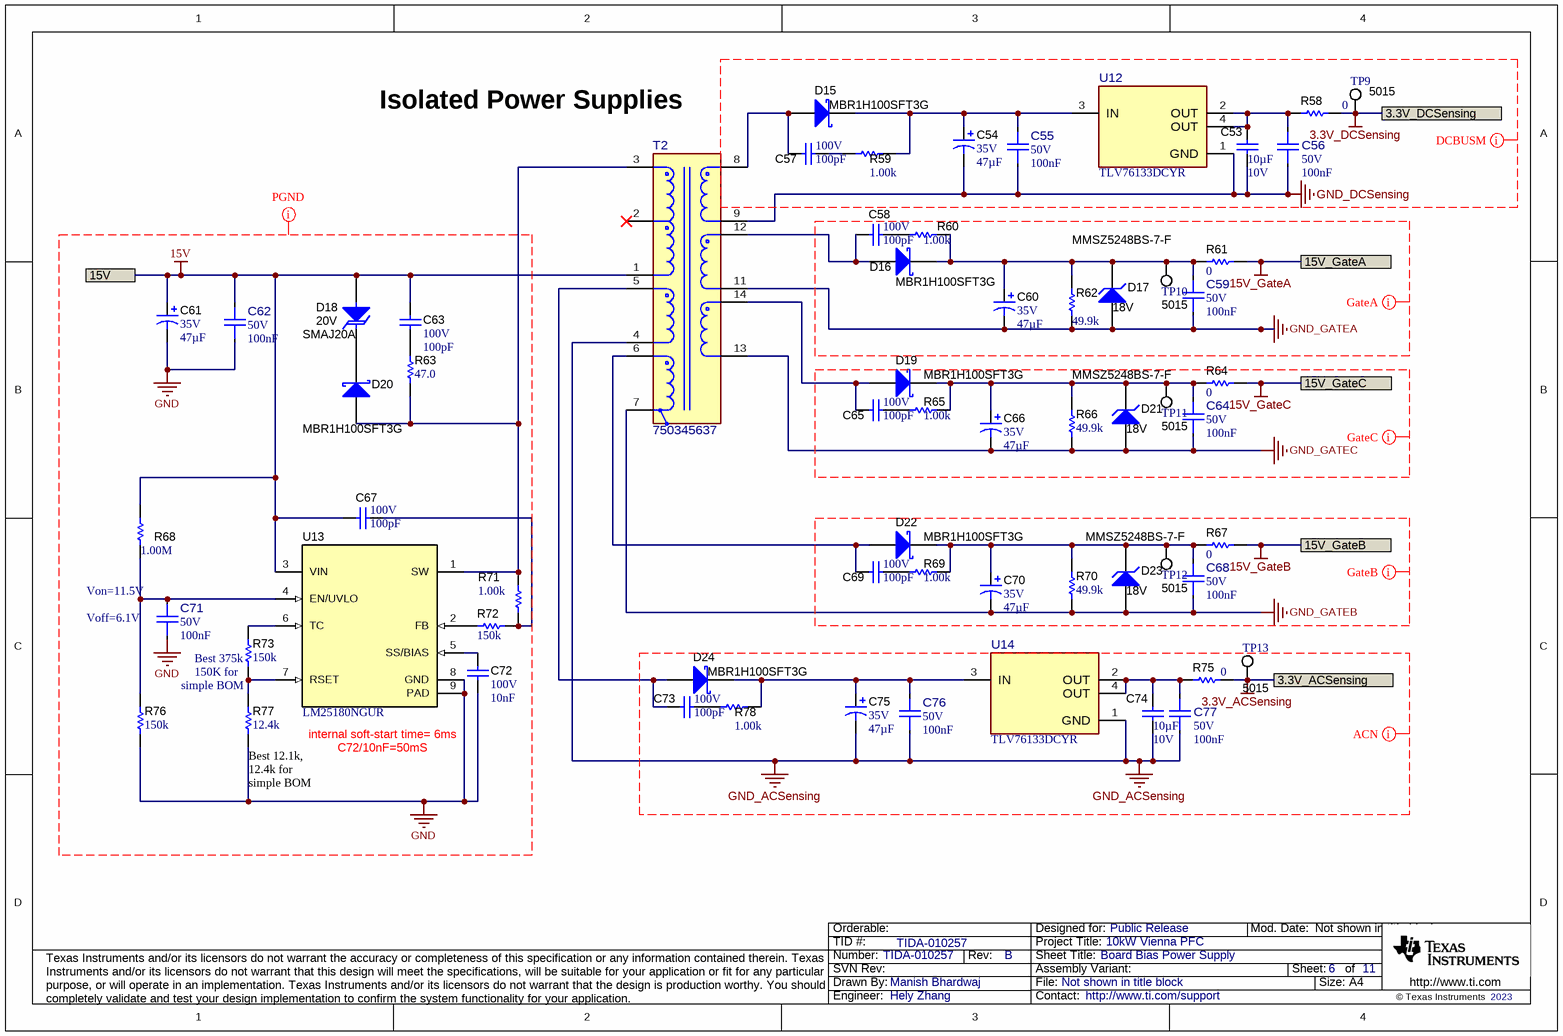
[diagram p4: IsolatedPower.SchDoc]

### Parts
C53  Cap_F: 10µF  VDC_V: 10V  [0603]  (hidden comment: GRM188Z71A106MA73D)
C54  VDC_V: 35V  ValueDisplayed: 47µF  [Chemi-Con_500x1100]  (hidden comment: EKZN350ELL470ME11D)
C55  VDC_V: 50V  Cap_F: 100nF  [FP-GCM188R71H104KA57J_0603-MFG]  (hidden comment: GCM188R71H104KA57J)
C56  VDC_V: 50V  Cap_F: 100nF  [FP-GCM188R71H104KA57J_0603-MFG]  (hidden comment: GCM188R71H104KA57J)
C57  VDC_V: 100V  ValueDisplayed: 100pF  [0603]  (hidden comment: GRM1885C2A101JA01D)
C58  VDC_V: 100V  ValueDisplayed: 100pF  [0603]  (hidden comment: GRM1885C2A101JA01D)
C59  VDC_V: 50V  Cap_F: 100nF  [FP-GCM188R71H104KA57J_0603-MFG]  (hidden comment: GCM188R71H104KA57J)
C60  VDC_V: 35V  ValueDisplayed: 47µF  [Chemi-Con_500x1100]  (hidden comment: EKZN350ELL470ME11D)
C61  VDC_V: 35V  ValueDisplayed: 47µF  [Chemi-Con_500x1100]  (hidden comment: EKZN350ELL470ME11D)
C62  VDC_V: 50V  Cap_F: 100nF  [FP-GCM188R71H104KA57J_0603-MFG]  (hidden comment: GCM188R71H104KA57J)
C63  VDC_V: 100V  ValueDisplayed: 100pF  [0603]  (hidden comment: GRM1885C2A101JA01D)
C64  VDC_V: 50V  Cap_F: 100nF  [FP-GCM188R71H104KA57J_0603-MFG]  (hidden comment: GCM188R71H104KA57J)
C65  VDC_V: 100V  ValueDisplayed: 100pF  [0603]  (hidden comment: GRM1885C2A101JA01D)
C66  VDC_V: 35V  ValueDisplayed: 47µF  [Chemi-Con_500x1100]  (hidden comment: EKZN350ELL470ME11D)
C67  VDC_V: 100V  ValueDisplayed: 100pF  [0603]  (hidden comment: GRM1885C2A101JA01D)
C68  VDC_V: 50V  Cap_F: 100nF  [FP-GCM188R71H104KA57J_0603-MFG]  (hidden comment: GCM188R71H104KA57J)
C69  VDC_V: 100V  ValueDisplayed: 100pF  [0603]  (hidden comment: GRM1885C2A101JA01D)
C70  VDC_V: 35V  ValueDisplayed: 47µF  [Chemi-Con_500x1100]  (hidden comment: EKZN350ELL470ME11D)
C71  VDC_V: 50V  Cap_F: 100nF  [FP-GCM188R71H104KA57J_0603-MFG]  (hidden comment: GCM188R71H104KA57J)
C72  VDC_V: 100V  Cap_F: 10nF  [0603]  (hidden comment: GCM188R72A103KA37J)
C73  VDC_V: 100V  ValueDisplayed: 100pF  [0603]  (hidden comment: GRM1885C2A101JA01D)
C74  Cap_F: 10µF  VDC_V: 10V  [0603]  (hidden comment: GRM188Z71A106MA73D)
C75  VDC_V: 35V  ValueDisplayed: 47µF  [Chemi-Con_500x1100]  (hidden comment: EKZN350ELL470ME11D)
C76  VDC_V: 50V  Cap_F: 100nF  [FP-GCM188R71H104KA57J_0603-MFG]  (hidden comment: GCM188R71H104KA57J)
C77  VDC_V: 50V  Cap_F: 100nF  [FP-GCM188R71H104KA57J_0603-MFG]  (hidden comment: GCM188R71H104KA57J)
D15  MBR1H100SFT3G  [SOD-123FL]
D16  MBR1H100SFT3G  [SOD-123FL]
D17  MMSZ5248BS-7-F  value 18V  [SOD-323]
D18  SMAJ20A  value 20V  [SMA]
D19  MBR1H100SFT3G  [SOD-123FL]
D20  MBR1H100SFT3G  [SOD-123FL]
D21  MMSZ5248BS-7-F  value 18V  [SOD-323]
D22  MBR1H100SFT3G  [SOD-123FL]
D23  MMSZ5248BS-7-F  value 18V  [SOD-323]
D24  MBR1H100SFT3G  [SOD-123FL]
R58  ValueDisplayed: 0  [0603]  (hidden comment: RC0603JR-070RL)
R59  ValueDisplayed: 1.00k  [0603]  (hidden comment: RC0603FR-071KL)
R60  ValueDisplayed: 1.00k  [0603]  (hidden comment: RC0603FR-071KL)
R61  ValueDisplayed: 0  [0603]  (hidden comment: RC0603JR-070RL)
R62  ValueDisplayed: 49.9k  [0603]  (hidden comment: RC0603FR-0749K9L)
R63  ValueDisplayed: 47.0  [1206]  (hidden comment: RC1206FR-0747RL)
R64  ValueDisplayed: 0  [0603]  (hidden comment: RC0603JR-070RL)
R65  ValueDisplayed: 1.00k  [0603]  (hidden comment: RC0603FR-071KL)
R66  ValueDisplayed: 49.9k  [0603]  (hidden comment: RC0603FR-0749K9L)
R67  ValueDisplayed: 0  [0603]  (hidden comment: RC0603JR-070RL)
R68  ValueDisplayed: 1.00M  [0805_HV]  (hidden comment: ERJ-6ENF1004V)
R69  ValueDisplayed: 1.00k  [0603]  (hidden comment: RC0603FR-071KL)
R70  ValueDisplayed: 49.9k  [0603]  (hidden comment: RC0603FR-0749K9L)
R71  ValueDisplayed: 1.00k  [0603]  (hidden comment: RC0603FR-071KL)
R72  ValueDisplayed: 150k  [0603]  (hidden comment: RC0603FR-07150KL)
R73  ValueDisplayed: 150k  [0603]  (hidden comment: RC0603FR-07150KL)
R75  ValueDisplayed: 0  [0603]  (hidden comment: RC0603JR-070RL)
R76  ValueDisplayed: 150k  [0603]  (hidden comment: RC0603FR-07150KL)
R77  ValueDisplayed: 12.4k  [0603]  (hidden comment: RC0603FR-0712K4L)
R78  ValueDisplayed: 1.00k  [0603]  (hidden comment: RC0603FR-071KL)
T2  750345637  [FP-750345637_PTH14-MFG]
TP9  5015  [Testpoint_Keystone_Miniature]
TP10  5015  [Testpoint_Keystone_Miniature]
TP11  5015  [Testpoint_Keystone_Miniature]
TP12  5015  [Testpoint_Keystone_Miniature]
TP13  5015  [Testpoint_Keystone_Miniature]
U12  TLV76133DCYR  [DCY0004A-MFG]
U13  LM25180NGUR  [NGU0008C]
U14  TLV76133DCYR  [DCY0004A-MFG]

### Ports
3.3V_ACSensing, 3.3V_DCSensing, 15V, 15V_GateA, 15V_GateB, 15V_GateC

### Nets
3.3V_ACSensing: R75.1 TP13.1 ; port 3.3V_ACSensing
3.3V_DCSensing: R58.1 TP9.1 ; port 3.3V_DCSensing
15V: C61.1(+) C62.2 C63.1 C67.2 D18.2(A) R68.2 T2.1 U13.3(VIN) ; port 15V
15V_GateA: R61.1 ; port 15V_GateA
15V_GateB: R67.1 ; port 15V_GateB
15V_GateC: R64.1 ; port 15V_GateC
GND: C61.2(-) C62.1 C71.1 C72.2 R76.1 R77.1 U13.8(GND) U13.9(PAD)  [project net VBUSN]
GND_ACSensing: C74.2 C75.2(-) C76.1 C77.1 T2.4 U14.1(GND)
GND_DCSensing: C53.2 C54.2(-) C55.1 C56.1 T2.9 U12.1(GND)  [project net VBUSM]
GND_GATEA: C59.1 C60.2(-) D17.2(A) R62.1 T2.11
GND_GATEB: C68.1 C70.2(-) D23.2(A) R70.1 T2.7
GND_GATEC: C64.1 C66.2(-) D21.2(A) R66.1 T2.13
NetC53_1: C53.1 C56.2 R58.2 U12.2(OUT) U12.4(OUT)
NetC54_1: C54.1(+) C55.2 D15.1(K) R59.2 U12.3(IN)
NetC57_1: C57.1 R59.1
NetC57_2: C57.2 D15.2(A) T2.8
NetC58_1: C58.1 R60.1
NetC58_2: C58.2 D16.2(A) T2.12
NetC59_2: C59.2 C60.1(+) D16.1(K) D17.1(K) R60.2 R61.2 R62.2 TP10.1
NetC63_2: C63.2 R63.2
NetC64_2: C64.2 C66.1(+) D19.1(K) D21.1(K) R64.2 R65.2 R66.2 TP11.1
NetC65_1: C65.1 R65.1
NetC65_2: C65.2 D19.2(A) T2.14
NetC67_1: C67.1 R71.1 R72.2
NetC68_2: C68.2 C70.1(+) D22.1(K) D23.1(K) R67.2 R69.2 R70.2 TP12.1
NetC69_1: C69.1 R69.1
NetC69_2: C69.2 D22.2(A) T2.6
NetC71_2: C71.2 R68.1 R76.2 U13.4(EN/UVLO)
NetC72_1: C72.1 U13.5(SS/BIAS)
NetC73_1: C73.1 R78.1
NetC73_2: C73.2 D24.2(A) T2.5
NetC74_1: C74.1 C77.2 R75.2 U14.2(OUT) U14.4(OUT)
NetC75_1: C75.1(+) C76.2 D24.1(K) R78.2 U14.3(IN)
NetD18_1: D18.1(K) D20.1(K)
NetD20_2: D20.2(A) R63.1 R71.2 T2.3 U13.1(SW)
NetR72_1: R72.1 U13.2(FB)
NetR73_1: R73.1 R77.2 U13.7(RSET)
NetR73_2: R73.2 U13.6(TC)

Not connected (* = marked no-connect by the designer): T2 2*

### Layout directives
net class GateA: 15V_GateA, GND_GATEA
net class GateB: 15V_GateB, GND_GATEB
net class GateC: 15V_GateC, GND_GATEC
net class ACN: 3.3V_ACSensing, GND_ACSensing
net class DCBUSM: 3.3V_DCSensing, GND_DCSensing
net class PGND: 15V, GND

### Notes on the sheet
- (near T2) Isolated Power Supplies
- Von=11.5V
- (near C71) Voff=6.1V
- simple BOM
- (near R73) Best 375k
- (near R73) 150K for
- internal soft-start time= 6ms
- (near U13) C72/10nF=50mS
- (near R77) Best 12.1k, 12.4k for simple BOM

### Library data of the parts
C53 C74 = CMP-0007497-5: CAP, CERM, 10 uF, 10 V, +/- 20%, X7R, 0603; Manufacturer: MuRata; TaMin_C: -55°C; Polarized: N; SizeAreaWB_mm2: 4.68; Value1: Unknown; U/M: EA; Value: 10uF; TaMax_C: 125°C; SizeZ_mm: 1; SizeX_mm: 1.6; SizeY_mm: 0.8; SizeArea_mm2: 1.28; AEC Category: Q200
C54 C60 C61 C66 C70 C75 = CMP-0074695-1: CAP, AL, 47 µF, 35 V, +/- 20%, 0.38 ohm, TH; Manufacturer: Chemi-Con; TaMin_C: -40°C; ESR_ohm: 0.38; Polarized: Y; SizeAreaWB_mm2: 49.0; U/M: EA; Value: 47uF; TaMax_C: 105°C; SizeZ_mm: 12.5; SizeX_mm: 5.0; Cap_Case: 5x11; SizeArea_mm2: 25.0; CompType: Capacitor; AEC Qualified: N; IRMS_A: 450mA; AEC Category: Q200
C55 C56 C59 C62 C64 C68 C71 C76 C77 = CMP-0095617-1: as C13 on sheet PowerStage
C57 C58 C63 C65 C67 C69 C73 = CMP-0007237-4: CAP, CERM, 100 pF, 100 V, +/- 5%, C0G/NP0, 0603; Manufacturer: MuRata; TaMin_C: -55°C; Polarized: N; SizeAreaWB_mm2: 4.68; Value1: Unknown; U/M: EA; Value: 100pF; TaMax_C: 125°C; SizeZ_mm: 1; SizeX_mm: 1.6; SizeY_mm: 0.8; SizeArea_mm2: 1.28; AEC Category: Q200
C72 = CMP-0084773-1: CAP, CERM, 0.01 µF, 100 V,+/- 10%, X7R, AEC-Q200 Grade 1, 0603; Manufacturer: MuRata; AEC Qualified: Y; SizeX_mm: 1.6; TaMin_C: -55°C; SizeArea_mm2: 1.28; AEC Category: Q200; ValueDisplayed: 0.01µF; SizeZ_mm: 1; Value: 0.01uF; Polarized: N; SizeAreaWB_mm2: 4.68; TaMax_C: 125°C; SizeY_mm: 0.8; U/M: EA
D15 D16 D19 D20 D22 D24 = CMP-0028625-2: Diode, Schottky, 100 V, 1 A, SOD-123FL; Manufacturer: ON Semiconductor; Value2: 0.76V; Vr_V: 100V; RJC_CperW: 85; SizeZ_mm: 0.98; Io_A: 1A; Green_Lifecycle: Active; SizeX_mm: 3.6; AEC Category: Q101; Vf_V: 760mV; SizeAreaWB_mm2: 12.19; SizeArea_mm2: 5.94; Green_REACh: Passed; Value: 100V; TJmax_C: 175°C; SizeY_mm: 1.65
D17 D21 D23 = CMP-0005835-4: Diode, Zener, 18 V, 200 mW, SOD-323; Manufacturer: Diodes Inc.; Value1: 0.2W; SizeArea_mm2: 3.645; AEC Category: Q101; Power_W: 200mW; SizeAreaWB_mm2: 8.695; SizeY_mm: 1.35; RJA_CperW: 350; SizeZ_mm: 1; SizeX_mm: 2.7
D18 = CMP-0084956-1: Diode, TVS, Uni, 20 V, 32.4 Vc, 400 W, 12.3 A, SMA; Manufacturer: Littelfuse; SizeZ_mm: 2.87; Value1: 32.4V; AEC Qualified: N; SizeX_mm: 5.59; Vbr_Max: 24.5V; Ipp: 12.3A; SizeY_mm: 2.92; Ppk: 400W; AEC Category: Q101; RJA_CperW: 120; Vbr_Min: 22.2V; SizeArea_mm2: 16.3228; SizeAreaWB_mm2: 37.3428
R58 R61 R64 R67 R75 = CMP-0025885-5: RES, 0, 5%, 0.1 W, 0603; Manufacturer: Yageo; Power_W: 100mW; TempCo: 200 ppm/C; Value_Code: 0000; Value: 0; EIA_Code: E24; SizeX_mm: 1.6; SizeZ_mm: 1; Value2: 0.1W; SizeArea_mm2: 1.28; AEC Qualified: N; VDC_V: 75V; AEC Category: Q200; SizeY_mm: 0.8; SizeAreaWB_mm2: 4.68
R59 R60 R65 R69 R71 R78 = CMP-0022895-5: as R13 on sheet PowerStage
R62 R66 R70 = CMP-0023142-5: RES, 49.9 k, 1%, 0.1 W, 0603; Manufacturer: Yageo; Power_W: 100mW; TempCo: 100 ppm/C; Value_Code: 49k9; Value: 49.9k; EIA_Code: E96; SizeX_mm: 1.6; SizeY_mm: 0.8; SizeZ_mm: 1; Value2: 0.1W; SizeArea_mm2: 1.28; AEC Qualified: N; VDC_V: 75V; AEC Category: Q200; SizeAreaWB_mm2: 4.68
R63 = CMP-0018320-2: RES, 47.0, 1%, 0.25 W, 1206; Manufacturer: Yageo America; Power_W: 250mW; TempCo: 100 ppm/C; Value_Code: 47R0; U/M: EA; Value: 47.0; Res_ohm: 47; SizeX_mm: 3.2; SizeY_mm: 1.6; SizeZ_mm: 1.35; Value2: 0.25W; SizeArea_mm2: 5.12; VDC_V: 200V; AEC Category: Q200
R68 = CMP-0021522-3: as R14 on sheet PowerStage
R72 R73 R76 = CMP-0022808-4: RES, 150 k, 1%, 0.1 W, 0603; Manufacturer: Yageo; Power_W: 100mW; TempCo: 100 ppm/C; Value: 150k; EIA_Code: E96; SizeX_mm: 1.6; SizeY_mm: 0.8; SizeZ_mm: 1; Value2: 0.1W; SizeArea_mm2: 1.28; AEC Qualified: N; VDC_V: 75V; AEC Category: Q200; SizeAreaWB_mm2: 4.68
R77 = CMP-0022777-5: RES, 12.4 k, 1%, 0.1 W, 0603; Manufacturer: Yageo; Power_W: 100mW; TempCo: 100 ppm/C; Value_Code: 12k4; Value: 12.4k; EIA_Code: E96; SizeX_mm: 1.6; SizeY_mm: 0.8; SizeZ_mm: 1; Value2: 0.1W; SizeArea_mm2: 1.28; AEC Qualified: N; VDC_V: 75V; AEC Category: Q200; SizeAreaWB_mm2: 4.68
T2 = CMP-0123200-1: TRANSFORMER; Manufacturer: Wurth Electornics; Ind_H: 39µH; Ns1toNp: 1:1.06; SizeZ_mm: 16mm; AEC Qualified: No; Frequency_Fixed: 180kHz
TP9-TP13 = CMP-0055152-2: as TP1 on sheet PowerStage
U12 U14 = CMP-0122558-1: 1-A 16-V high-PSRR linear voltage regulator 4-SOT-223 -40 to 125; Manufacturer: Texas Instruments; SizeZ_mm: 1.8mm; AEC Qualified: No; Accuracy Percentage: 1%; Dropout Voltage: 0.9V; Max Supply Voltage: 16V; Min Supply Voltage: 4.8V; Nominal Supply Current: 65uA; Number Of Outputs: 1; Output Type: Fixed; Output Voltage: 3.3V; Standoff Height: 0.02mm; TJmax_C: +125°C
U13 = CMP-0750185-1: LM25180 42-VIN PSR Flyback DC/DC Converter With 65-V, 1.5-A Integrated Power MOSFET, NGU0008C (WSON-8); Alternate Manufacturer: Texas Instruments; Alternate PartNumber: LM25180NGUT; CompType: IC; SizeArea_mm2: 16; AEC Qualified: N; SizeAreaWB_mm2: 25; AEC Category: Q200; SizeX_mm: 4; SizeZ_mm: 0.8

## Sheet Hardware.SchDoc: EVM Hardware
size 431 x 279 mm; Date: Not shown in title block; ApprovedBy: Not shown in title block; CheckedBy: Not shown in title block; Author: Not shown in title block; CompanyName: Not shown in title block; DrawnBy: Manish Bhardwaj; Engineer: Not shown in title block; Organization: Not shown in title block; Address1: Not shown in title block; Address2: Not shown in title block; Address3: Not shown in title block; Address4: Not shown in title block; DocumentNumber: 1; Revision: Use project parameter SCH_Rev; SheetNumber: 11; SheetTotal: 11; PageSetup: Record=PageOptions¦CenterHorizontal=True¦CenterVertical=True¦PrintScale=1.00¦XCorrection=1.00¦YCorrection=1.00¦PrintKind=0¦BorderSize=5000000¦LeftOffset=0¦BottomOffset=0¦Orientation=2¦PaperLength=1000¦PaperWidth=1000¦Scale=100¦PaperSource=15¦PrintQuality=600¦MediaType=1¦DitherType=10¦PaperKind=Letter¦PrintScaleMode=1
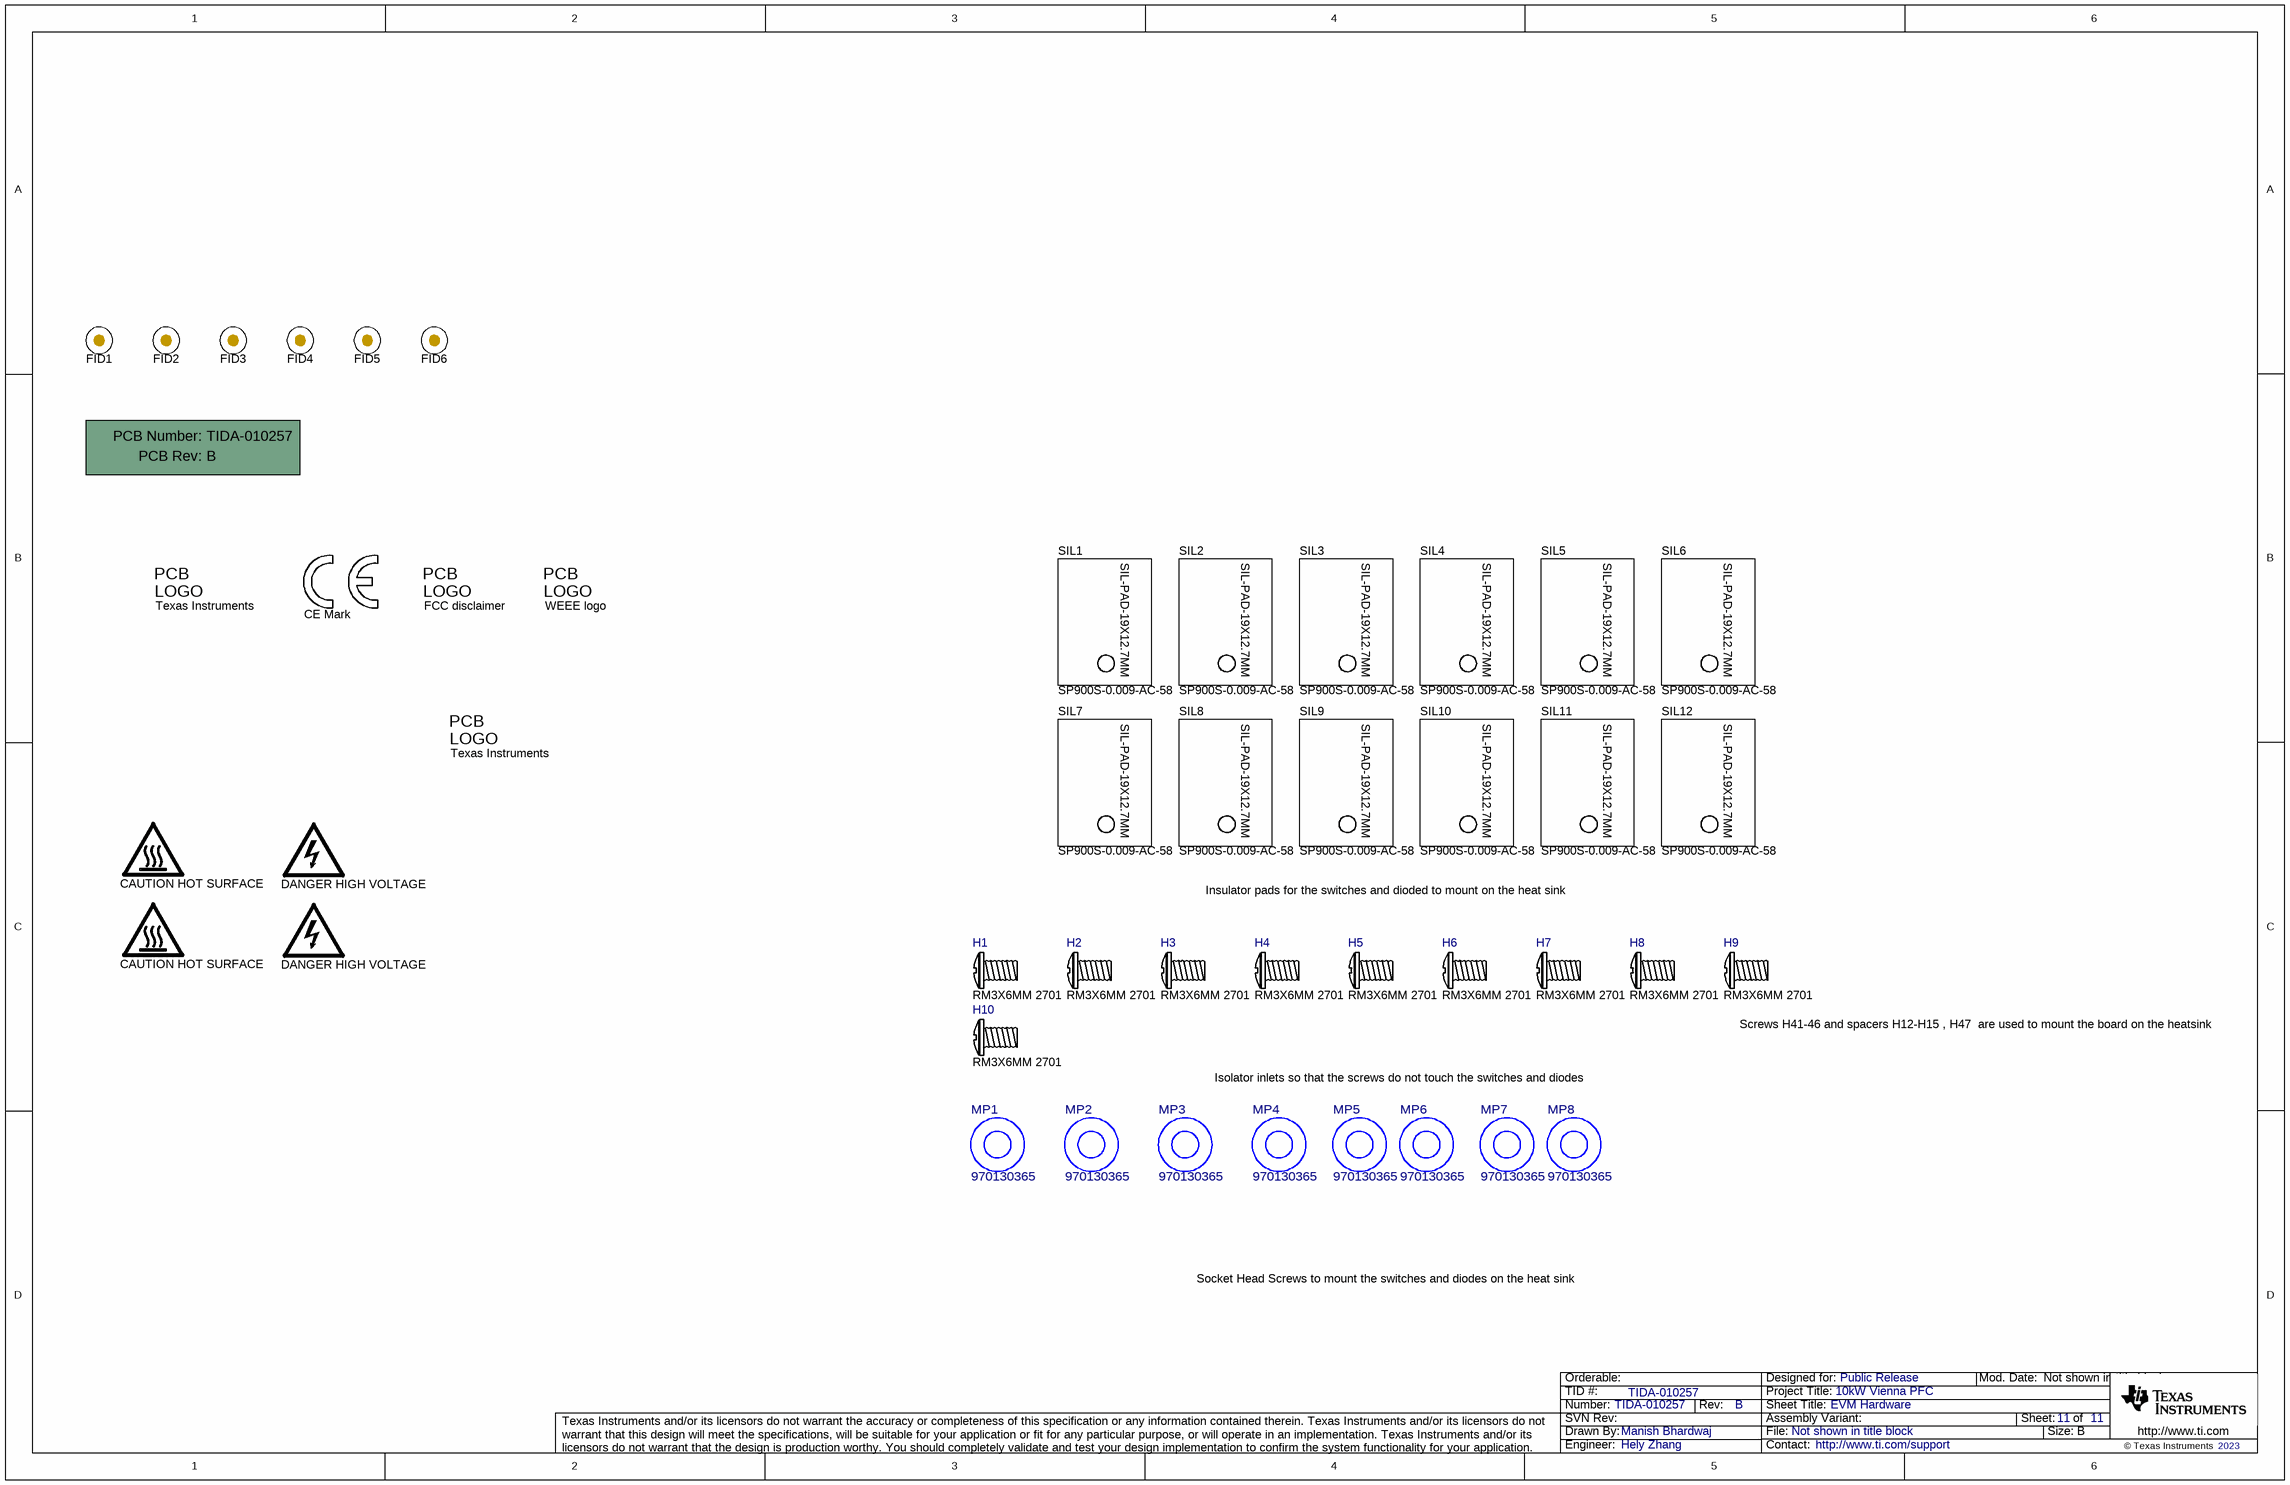
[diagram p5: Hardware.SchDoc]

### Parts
FID1  Fiducial  [Fiducial10-20]  (value not drawn)
FID2  Fiducial  [Fiducial10-20]  (value not drawn)
FID3  Fiducial  [Fiducial10-20]  (value not drawn)
FID4  Fiducial  [Fiducial10-20]  (value not drawn)
FID5  Fiducial  [Fiducial10-20]  (value not drawn)
FID6  Fiducial  [Fiducial10-20]  (value not drawn)
H1  RM3X6MM 2701  (mechanical)
H2  RM3X6MM 2701  (mechanical)
H3  RM3X6MM 2701  (mechanical)
H4  RM3X6MM 2701  (mechanical)
H5  RM3X6MM 2701  (mechanical)
H6  RM3X6MM 2701  (mechanical)
H7  RM3X6MM 2701  (mechanical)
H8  RM3X6MM 2701  (mechanical)
H9  RM3X6MM 2701  (mechanical)
H10  RM3X6MM 2701  (mechanical)
Logo1  CE Mark  [CE_Mark_5mm]  (no BOM)
Logo2  Texas Instruments  [TI_Stacked_Overlay_Small]  (no BOM)
Logo3  FCC disclaimer  [FCC_disclaimer]  (no BOM)
Logo4  WEEE logo  [WEEE_Minimum]  (no BOM)
Logo5  Texas Instruments  [TI_Stacked_Overlay_Small]  (no BOM)
LOGO6  CAUTION HOT SURFACE  [IEC_HotSurface_Small]  (no BOM)
LOGO7  DANGER HIGH VOLTAGE  [IEC_HighVoltage_Small]  (no BOM)
LOGO8  CAUTION HOT SURFACE  [IEC_HotSurface_Small]  (no BOM)
LOGO9  DANGER HIGH VOLTAGE  [IEC_HighVoltage_Small]  (no BOM)
MP1  970130365  [FP-970130365_SPCAER_M3-MFG]
MP2  970130365  [FP-970130365_SPCAER_M3-MFG]
MP3  970130365  [FP-970130365_SPCAER_M3-MFG]
MP4  970130365  [FP-970130365_SPCAER_M3-MFG]
MP5  970130365  [FP-970130365_SPCAER_M3-MFG]
MP6  970130365  [FP-970130365_SPCAER_M3-MFG]
MP7  970130365  [FP-970130365_SPCAER_M3-MFG]
MP8  970130365  [FP-970130365_SPCAER_M3-MFG]
SIL1  SP900S-0.009-AC-58  [SIL-PAD_19x12.7mm]
SIL2  SP900S-0.009-AC-58  [SIL-PAD_19x12.7mm]
SIL3  SP900S-0.009-AC-58  [SIL-PAD_19x12.7mm]
SIL4  SP900S-0.009-AC-58  [SIL-PAD_19x12.7mm]
SIL5  SP900S-0.009-AC-58  [SIL-PAD_19x12.7mm]
SIL6  SP900S-0.009-AC-58  [SIL-PAD_19x12.7mm]
SIL7  SP900S-0.009-AC-58  [SIL-PAD_19x12.7mm]
SIL8  SP900S-0.009-AC-58  [SIL-PAD_19x12.7mm]
SIL9  SP900S-0.009-AC-58  [SIL-PAD_19x12.7mm]
SIL10  SP900S-0.009-AC-58  [SIL-PAD_19x12.7mm]
SIL11  SP900S-0.009-AC-58  [SIL-PAD_19x12.7mm]
SIL12  SP900S-0.009-AC-58  [SIL-PAD_19x12.7mm]
TIDA-1  Printed Circuit Board of the Design  (value not drawn)  (mechanical)

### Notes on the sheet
- Insulator pads for the switches and dioded to mount on the heat sink
- (near H9) Screws H41-46 and spacers H12-H15 , H47  are used to mount the board on the heatsink
- Isolator inlets so that the screws do not touch the switches and diodes
- Socket Head Screws to mount the switches and diodes on the heat sink

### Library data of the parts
FID1-FID6 = CMP-0077181-1: Fiducial mark.  There is nothing to buy or mount.
H1-H10 = CMP-0077936-1: MACHINE SCREW PAN PHILLIPS M3; Manufacturer: APM HEXSEAL; CompType: Standoff
Logo1 = CMP-0074844-1: SymbolCreator: a0412235
Logo2 Logo5 = CMP-0074838-1: Texas Instrument Corporate Signature; SymbolCreator: a0412235; Lib Reference: TI_Logo; Library Reference: Logo
Logo3 = CMP-0074847-1: FCC_disclaimer; Library Reference: Logo
Logo4 = CMP-0074769-1
LOGO6 LOGO8 = CMP-0074837-1: IEC 61010-1 Hot Surface Warning; SymbolCreator: a0412235; Lib Reference: IEC_HotSurface
LOGO7 LOGO9 = CMP-0074835-1: IEC 61010-1 High Voltage Warning; SymbolCreator: a0412235; Lib Reference: IEC_HighVoltage
MP1-MP8 = CMP-0087151-1: Manufacturer: Wurth Electronics
SIL1-SIL12 = CMP-0003919-1: Silcon Thermal Pad; Manufacturer: Bergquist Company
TIDA-1 = PCB: 250*260mm 1OZ double sides PCB; Manufacturer: Any; PartNumber: MCU011; SymbolCreator: a0412235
